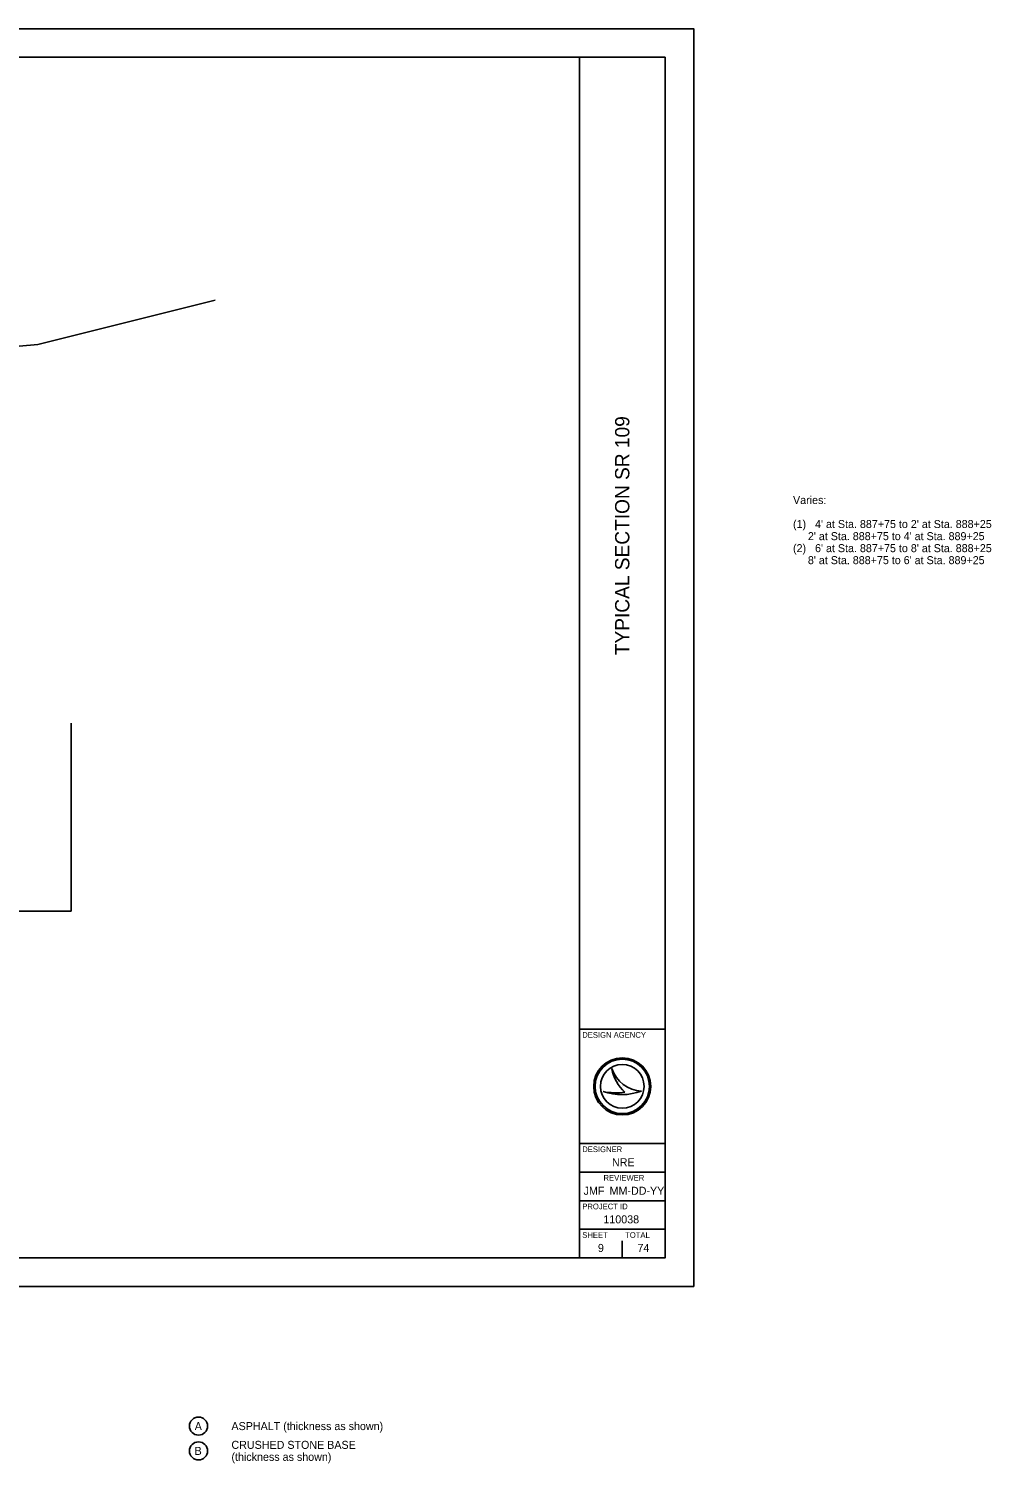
# Model space of a CAD drawing. Extents: x -54 to 196, y -24 to 110.
# Drawn here: x 111.9 to 196, y -15.5 to 110 of the extents above; entities that cross this region are included whole.
import ezdxf

# ---------------------------------------------------------------- set-up
doc = ezdxf.new("R2010")
doc.units = 0
for name, color, linetype in [('Default', 7, 'Continuous'), ('SH_Border', 7, 'Continuous'), ('SH_Cut_Line', 7, 'Continuous'), ('SH_Data', 7, 'Continuous'), ('SH_Text', 7, 'Continuous'), ('XS_X_Ground_Line', 7, 'Continuous')]:
    doc.layers.add(name, color=color, linetype=linetype)

msp = doc.modelspace()

# ---------------------------------------------------------------- linework, layer by layer
at = {"layer": 'Default'}
for p, q in [((115.57, 32.81), (115.57, 49.27)), ((105.07, 32.81), (115.57, 32.81))]:
    msp.add_line(p, q, dxfattribs=at)
for centre in [(126.7, -12.21), (126.7, -14.38)]:
    msp.add_circle(centre, 0.793, dxfattribs=at)
at = {"layer": 'SH_Border'}
for p, q in [((160, 2.5), (160, 107.5)), ((160, 22.5), (167.5, 22.5)), ((160, 12.5), (167.5, 12.5)), ((160, 10), (167.5, 10)), ((160, 7.5), (167.5, 7.5)), ((160, 5), (167.5, 5))]:
    msp.add_line(p, q, dxfattribs=at)
msp.add_lwpolyline([(7.5, 107.5), (167.5, 107.5), (167.5, 2.5), (7.5, 2.5)], close=True, dxfattribs=at)
at = {"layer": 'SH_Cut_Line'}
msp.add_lwpolyline([(0, 0), (170, 0), (170, 110), (0, 110)], close=True, dxfattribs=at)
at = {"layer": 'SH_Data'}
for p, q in [((162.84, 19.05), (162.84, 19.05)), ((162.09, 17.05), (162.09, 17.05)), ((163.75, 17.5), (163.75, 17.5)), ((165.44, 17.09), (165.44, 17.09)), ((163.75, 2.5), (163.75, 4)), ((161.87, 3.38), (161.87, 3.38))]:
    msp.add_line(p, q, dxfattribs=at)
for radius in [2.5, 2.38, 2.38, 1.91]:
    msp.add_circle((163.75, 17.5), radius, dxfattribs=at)
for centre, radius, start, end in [((165.58, 19.99), 2.9, 198.9257, 198.9319), ((166.73, 19.85), 3.98, 191.6379, 191.6421), ((165.58, 19.99), 2.9, 198.9319, 267.1657), ((166.73, 19.85), 3.98, 191.6421, 226.0947), ((163.7, 21.85), 5.07, 251.4576, 290.0832), ((163.24, 23.27), 6.33, 259.4964, 259.4995), ((163.7, 21.85), 5.07, 251.4527, 251.4576), ((163.24, 23.27), 6.33, 259.4995, 276.6672)]:
    msp.add_arc(centre, radius, start, end, dxfattribs=at)
at = {"layer": 'XS_X_Ground_Line'}
for q in [(128.16, 86.25), (106.16, 81.83)]:
    msp.add_line((112.65, 82.37), q, dxfattribs=at)

# ---------------------------------------------------------------- texts
at = {"layer": 'SH_Data'}
msp.add_text('TYPICAL SECTION SR 109', height=1.25, rotation=90, dxfattribs=at).set_placement((164.37, 55.21))
for s, height, p in [('DESIGN AGENCY', 0.5, (160.25, 21.75)), ('DESIGNER', 0.5, (160.25, 11.75)), ('NRE', 0.7, (162.85, 10.52)), ('REVIEWER', 0.5, (162.11, 9.25)), ('JMF', 0.7, (160.37, 8.02)), ('MM-DD-YY', 0.7, (162.64, 8.02)), ('PROJECT ID', 0.5, (160.25, 6.75)), ('110038', 0.7, (162.1, 5.52)), ('SHEET', 0.5, (160.25, 4.25)), ('TOTAL', 0.5, (164, 4.25)), ('9', 0.7, (161.62, 3.02)), ('74', 0.7, (165.08, 3.02))]:
    msp.add_text(s, height=height, dxfattribs=at).set_placement(p)
at = {"layer": 'SH_Text'}
for s, p in [('Varies:', (178.68, 68.43)), ("(1)   4' at Sta. 887+75 to 2' at Sta. 888+25", (178.68, 66.33)), ("     2' at Sta. 888+75 to 4' at Sta. 889+25", (178.68, 65.27)), ("(2)   6' at Sta. 887+75 to 8' at Sta. 888+25", (178.68, 64.22)), ("     8' at Sta. 888+75 to 6' at Sta. 889+25", (178.68, 63.17)), ('A', (126.37, -12.56)), ('ASPHALT (thickness as shown)', (129.58, -12.56)), ('CRUSHED STONE BASE ', (129.58, -14.2)), ('B', (126.36, -14.73)), ('(thickness as shown)', (129.58, -15.25))]:
    msp.add_text(s, height=0.7, dxfattribs=at).set_placement(p)

doc.saveas('drawing.dxf')
